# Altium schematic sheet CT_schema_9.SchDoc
size 281 x 153 mm
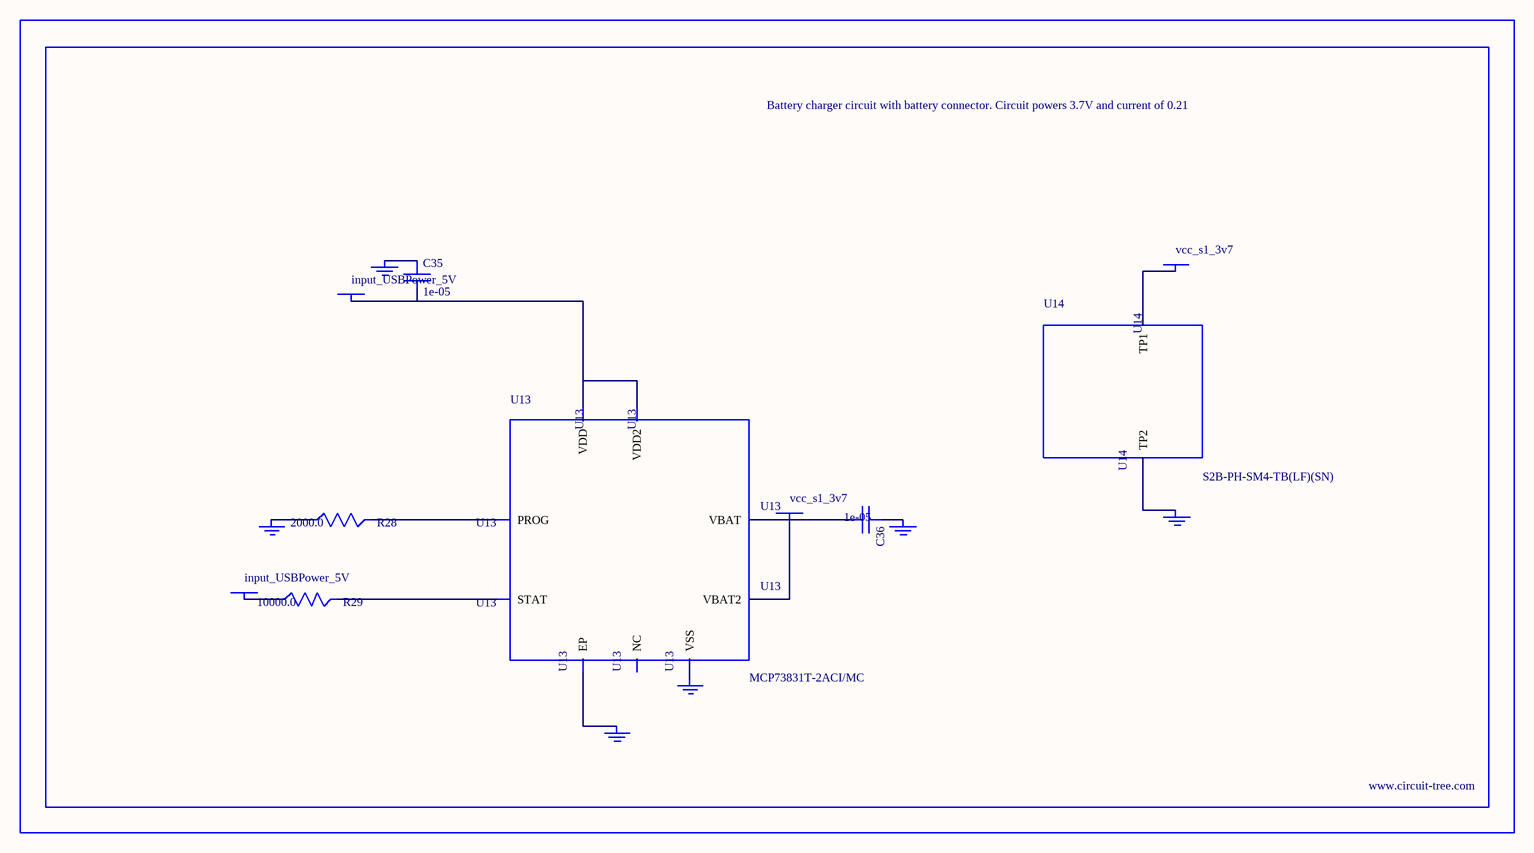
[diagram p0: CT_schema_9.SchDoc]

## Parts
BORDER8  (no value)
C35  1e-05  [C1206]
C36  1e-05  [C1206]
GND_INSTANCE_8_0  (no value)
GND_INSTANCE_8_1  (no value)
GND_INSTANCE_8_2  (no value)
GND_INSTANCE_8_3  (no value)
GND_INSTANCE_8_4  (no value)
GND_INSTANCE_8_5  (no value)
POWER_INSTANCE_8_0  input_USBPower_5V
POWER_INSTANCE_8_1  input_USBPower_5V
POWER_INSTANCE_8_2  vcc_s1_3v7
POWER_INSTANCE_8_3  vcc_s1_3v7
R28  2000.0  [R0603]
R29  10000.0  [R0603]
U13  MCP73831T-2ACI/MC  [DFN8_2X3MC]
U14  S2B-PH-SM4-TB(LF)(SN)  [JST-2-SMD]

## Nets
NetC35_1: C35.1 GND_INSTANCE_8_0.0(GND)
NetC35_2: C35.2 POWER_INSTANCE_8_0.0(PWR) U13.1(VDD) U13.2(VDD2)
NetC36_1: C36.1 GND_INSTANCE_8_1.0(GND)
NetC36_2: C36.2 POWER_INSTANCE_8_2.0(PWR) U13.3(VBAT) U13.4(VBAT2)
NetGND_INSTANCE_8_2_0: GND_INSTANCE_8_2.0(GND) R28.1
NetGND_INSTANCE_8_3_0: GND_INSTANCE_8_3.0(GND) U13.9(EP)
NetGND_INSTANCE_8_4_0: GND_INSTANCE_8_4.0(GND) U13.6(VSS)
NetGND_INSTANCE_8_5_0: GND_INSTANCE_8_5.0(GND) U14.2(TP2)
NetPOWER_INSTANCE_8_1_0: POWER_INSTANCE_8_1.0(PWR) R29.1
NetPOWER_INSTANCE_8_3_0: POWER_INSTANCE_8_3.0(PWR) U14.1(TP1)
NetR28_2: R28.2 U13.8(PROG)
NetR29_2: R29.2 U13.5(STAT)

Not connected (* = marked no-connect by the designer): U13 7(NC)

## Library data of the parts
BORDER8 = BORDER_PAGE8
C35 C36 = C1206C106K3RACTU
GND_INSTANCE_8_0-GND_INSTANCE_8_5 = GND
POWER_INSTANCE_8_0-POWER_INSTANCE_8_3 = PWR
R28 = RC0603JR-072KL
R29 = RC0603JR-0710KL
